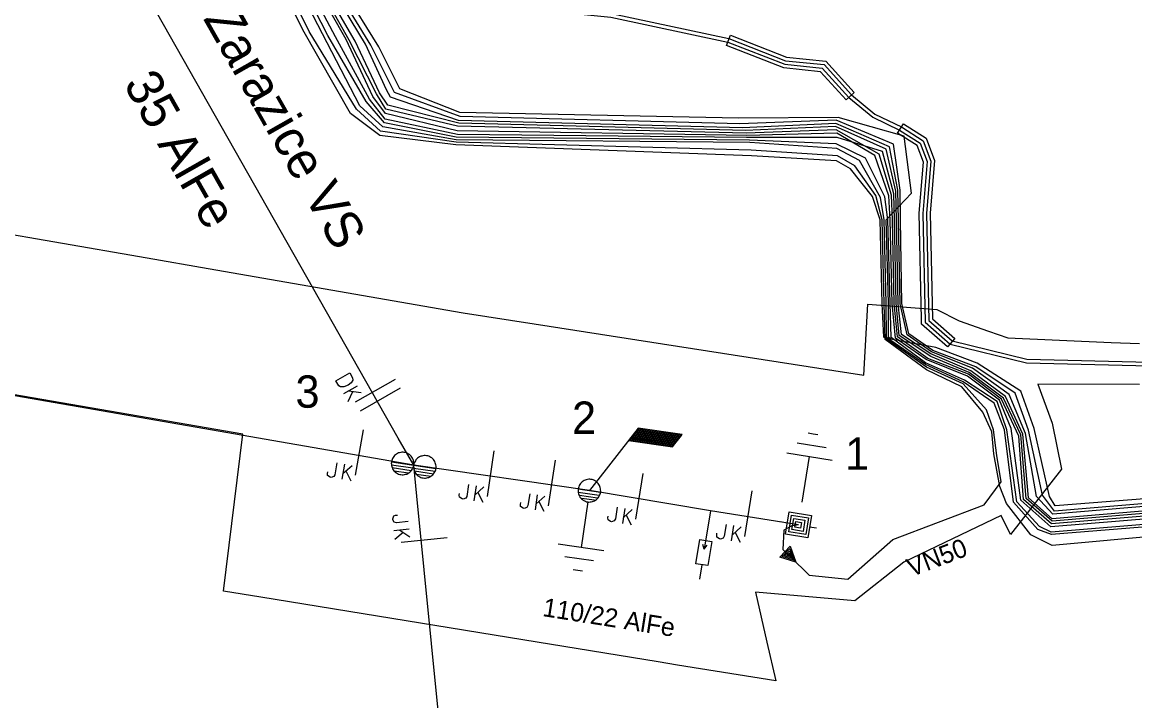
# Model space of a CAD drawing. Extents: x -545588 to -543214, y -1196037 to -1194452.
# Drawn here: x -545323 to -545262.7, y -1194915.7 to -1194878.9 of the extents above; entities that cross this region are included whole.
import ezdxf

# ---------------------------------------------------------------- set-up
doc = ezdxf.new("R2010")
doc.units = 0
for name, color, linetype in [('CIZÍ_NADZEM', 7, 'Continuous'), ('DOPLŇ_POPISY', 7, 'Continuous'), ('ELE_EON', 7, 'Continuous'), ('ELE_EON_POPIS', 7, 'Continuous'), ('Implicitní', 7, 'Continuous'), ('POL_ZNAČKA_PRACOVNÍ', 7, 'Continuous'), ('POL_ČÍSLO_PRACOVNÍ', 7, 'Continuous'), ('SDEL_EON_POPIS', 7, 'Continuous'), ('TECH_OCHR_PÁSMO_HRAN', 7, 'Continuous'), ('Vrstva 18', 7, 'Continuous'), ('Vrstva 19', 7, 'Continuous'), ('Vrstva 20', 7, 'Continuous'), ('Vrstva 35', 7, 'Continuous'), ('Vrstva 52', 7, 'Continuous'), ('Vrstva 53', 7, 'Continuous'), ('Vrstva 54', 7, 'Continuous'), ('ZP_EON', 7, 'Continuous')]:
    doc.layers.add(name, color=color, linetype=linetype)

# ---------------------------------------------------------------- blocks, each defined once
blk = doc.blocks.new('VN850')
at = {"layer": 'POL_ZNAČKA_PRACOVNÍ'}
for points in [[(-0.565, 1.426), (-0.565, -1.074)], [(-0.014, 1.426), (-0.014, -1.074)], [(-2.091, -0.542), (-1.776, -0.542)], [(-2.091, -1.409), (-2.091, -0.542)], [(-1.776, -0.542), (-1.657, -0.602)], [(-1.657, -0.602), (-1.588, -0.749)], [(-1.264, -0.542), (-1.264, -1.409)], [(-0.85, -0.542), (-1.264, -1.094)], [(-1.588, -1.202), (-1.667, -1.35)], [(-1.588, -0.749), (-1.549, -0.956)], [(-1.549, -0.956), (-1.588, -1.202)], [(-1.126, -0.917), (-0.772, -1.409)], [(-1.776, -1.409), (-2.091, -1.409)], [(-1.667, -1.35), (-1.776, -1.409)]]:
    blk.add_lwpolyline(points, dxfattribs=at)
blk = doc.blocks.new('VN840')
at = {"layer": 'POL_ZNAČKA_PRACOVNÍ'}
for points in [[(-0.009, 1.414), (-0.009, -1.086)], [(-1.092, -0.594), (-1.092, -1.243)], [(-0.678, -0.594), (-0.678, -1.421)], [(-0.678, -1.106), (-0.265, -0.594)], [(-1.505, -1.243), (-1.505, -1.145)], [(-0.541, -0.938), (-0.196, -1.421)], [(-1.476, -1.352), (-1.505, -1.243)], [(-1.328, -1.421), (-1.476, -1.352)], [(-1.269, -1.421), (-1.328, -1.421)], [(-1.131, -1.352), (-1.269, -1.421)], [(-1.092, -1.243), (-1.131, -1.352)]]:
    blk.add_lwpolyline(points, dxfattribs=at)
blk = doc.blocks.new('VN890')
at = {"layer": 'SDEL_EON_POPIS'}
for points in [[(-0.409, 0.411), (0.411, 0.001)], [(-0.409, -0.409), (-0.409, 0.411)], [(0.411, 0.001), (-0.409, -0.409)], [(-0.345, 0.31), (0.265, -0.003), (-0.345, -0.296), (-0.345, 0.31)], [(-0.264, 0.204), (0.104, 0.001), (-0.264, -0.183), (-0.264, 0.204)], [(-0.193, 0.094), (-0.045, 0.004), (-0.193, -0.08), (-0.193, 0.094)], [(-0.158, -0.009), (-0.158, 0.03), (-0.129, 0.007), (-0.158, -0.009)]]:
    blk.add_lwpolyline(points, dxfattribs=at)
blk = doc.blocks.new('VN820')
at = {"layer": 'DOPLŇ_POPISY'}
for points in [[(0.003, 0.002), (0.003, -2.105)], [(-0.322, -1.632), (0.338, -1.632)], [(-0.322, -2.951), (-0.322, -1.632)], [(0.338, -1.632), (0.338, -2.951)], [(0.003, -2.105), (-0.115, -1.859)], [(0.003, -2.105), (0.121, -1.859)], [(0.338, -2.951), (-0.322, -2.951)], [(0.003, -2.951), (0.003, -3.748)]]:
    blk.add_lwpolyline(points, dxfattribs=at)
blk = doc.blocks.new('VN810')
at = {"layer": 'POL_ZNAČKA_PRACOVNÍ'}
for points in [[(0.004, -1.247), (0.004, -3.747)], [(1.254, -3.747), (-1.246, -3.747)], [(0.772, -4.367), (-0.803, -4.367)], [(0.004, -4.997), (-0.252, -4.997)], [(0.27, -4.997), (0.004, -4.997)]]:
    blk.add_lwpolyline(points, dxfattribs=at)
blk = doc.blocks.new('VN450')
at = {"layer": 'ELE_EON_POPIS'}
for points in [[(0, 0), (-0.01, 0.13), (-0.03, 0.25), (-0.06, 0.38), (-0.11, 0.5), (-0.16, 0.61), (-0.23, 0.72), (-0.31, 0.82), (-0.4, 0.91), (-0.5, 0.99), (-0.61, 1.06), (-0.72, 1.11), (-0.84, 1.16), (-0.97, 1.19), (-1.09, 1.21), (-1.22, 1.22), (-1.35, 1.21), (-1.47, 1.19), (-1.59, 1.16), (-1.71, 1.11), (-1.83, 1.06), (-1.93, 0.99), (-2.03, 0.91), (-2.12, 0.82), (-2.2, 0.72), (-2.27, 0.61), (-2.33, 0.5), (-2.38, 0.38), (-2.41, 0.25), (-2.43, 0.13), (-2.44, 0), (-2.43, -0.13), (-2.41, -0.25), (-2.38, -0.38), (-2.33, -0.5), (-2.27, -0.61), (-2.2, -0.72), (-2.12, -0.82), (-2.03, -0.91), (-1.93, -0.99), (-1.83, -1.06), (-1.71, -1.11), (-1.59, -1.16), (-1.47, -1.19), (-1.35, -1.21), (-1.22, -1.22), (-1.09, -1.21), (-0.97, -1.19), (-0.84, -1.16), (-0.72, -1.11), (-0.61, -1.06), (-0.5, -0.99), (-0.4, -0.91), (-0.31, -0.82), (-0.23, -0.72), (-0.16, -0.61), (-0.11, -0.5), (-0.06, -0.38), (-0.03, -0.25), (-0.01, -0.13), (0, 0)], [(2.44, 0), (2.43, 0.13), (2.41, 0.25), (2.38, 0.38), (2.33, 0.5), (2.27, 0.61), (2.2, 0.72), (2.12, 0.82), (2.03, 0.91), (1.94, 0.99), (1.83, 1.06), (1.71, 1.11), (1.6, 1.16), (1.47, 1.19), (1.35, 1.21), (1.22, 1.22), (1.09, 1.21), (0.97, 1.19), (0.84, 1.16), (0.72, 1.11), (0.61, 1.06), (0.5, 0.99), (0.4, 0.91), (0.31, 0.82), (0.23, 0.72), (0.16, 0.61), (0.11, 0.5), (0.06, 0.38), (0.03, 0.25), (0.01, 0.13), (0, 0), (0.01, -0.13), (0.03, -0.25), (0.06, -0.38), (0.11, -0.5), (0.16, -0.61), (0.23, -0.72), (0.31, -0.82), (0.4, -0.91), (0.5, -0.99), (0.61, -1.06), (0.72, -1.11), (0.84, -1.16), (0.97, -1.19), (1.09, -1.21), (1.22, -1.22), (1.35, -1.21), (1.47, -1.19), (1.6, -1.16), (1.71, -1.11), (1.83, -1.06), (1.94, -0.99), (2.03, -0.91), (2.12, -0.82), (2.2, -0.72), (2.27, -0.61), (2.33, -0.5), (2.38, -0.38), (2.41, -0.25), (2.43, -0.13), (2.44, 0)], [(-2.44, 0), (2.44, 0)], [(-2.4, -0.31), (-0.04, -0.31)], [(-2.26, -0.61), (-0.17, -0.61)], [(-2.01, -0.92), (-0.42, -0.92)], [(0.04, -0.31), (2.4, -0.31)], [(0.17, -0.61), (2.27, -0.61)], [(0.42, -0.92), (2.02, -0.92)]]:
    blk.add_lwpolyline(points, dxfattribs=at)
blk = doc.blocks.new('VN001')
at = {"layer": 'Implicitní'}
for p, q in [((2.074, 3.631), (4.49, 3.631)), ((2.103, 3.681), (4.519, 3.681)), ((2.132, 3.731), (2.543, 3.731)), ((1.732, 3.031), (4.144, 3.031)), ((1.76, 3.081), (4.173, 3.081)), ((1.789, 3.131), (4.201, 3.131)), ((1.817, 3.181), (4.23, 3.181)), ((1.846, 3.231), (4.259, 3.231)), ((1.874, 3.281), (4.288, 3.281)), ((1.903, 3.331), (4.317, 3.331)), ((1.932, 3.381), (4.346, 3.381)), ((1.96, 3.431), (4.375, 3.431)), ((1.989, 3.481), (4.403, 3.481)), ((2.017, 3.531), (4.432, 3.531)), ((2.046, 3.581), (4.461, 3.581))]:
    blk.add_line(p, q, dxfattribs=at)
blk.add_lwpolyline([(2.132, 3.732), (0, 0)], dxfattribs=at)
blk.add_lwpolyline([(4.545, 3.727), (2.132, 3.732), (1.705, 2.984), (4.117, 2.985)], close=True, dxfattribs=at)
blk = doc.blocks.new('VN470')
at = {"layer": 'ELE_EON_POPIS'}
for points in [[(-1.23, 1.22), (1.23, 1.22)], [(-1.23, -1.23), (-1.23, 1.22)], [(0, 1.22), (0, 1.97)], [(1.23, 1.22), (1.23, -1.23)], [(-0.92, 0.9), (0.92, 0.9)], [(-0.92, -0.95), (-0.92, 0.9)], [(-0.61, 0.61), (0.61, 0.61)], [(-0.61, -0.62), (-0.61, 0.61)], [(-0.31, -0.27), (-0.31, 0.34)], [(-0.31, 0.34), (0.31, 0.34)], [(0.31, 0.34), (0.31, -0.27)], [(0.61, 0.61), (0.61, -0.62)], [(0.92, 0.9), (0.92, -0.95)], [(0.92, -0.95), (-0.92, -0.95)], [(0.61, -0.62), (-0.61, -0.62)], [(0.31, -0.27), (-0.31, -0.27)], [(1.23, -1.23), (-1.23, -1.23)], [(0, -1.23), (0, -1.98)]]:
    blk.add_lwpolyline(points, dxfattribs=at)
blk = doc.blocks.new('VN440')
at = {"layer": 'ELE_EON_POPIS'}
for points in [[(1.22, 0), (1.21, 0.13), (1.19, 0.25), (1.16, 0.38), (1.11, 0.5), (1.05, 0.61), (0.98, 0.72), (0.9, 0.82), (0.81, 0.91), (0.71, 0.99), (0.6, 1.06), (0.49, 1.12), (0.37, 1.16), (0.25, 1.2), (0.12, 1.22), (-0.01, 1.22), (-0.14, 1.22), (-0.26, 1.2), (-0.39, 1.16), (-0.51, 1.12), (-0.62, 1.06), (-0.73, 0.99), (-0.83, 0.91), (-0.92, 0.82), (-1, 0.72), (-1.07, 0.61), (-1.13, 0.5), (-1.18, 0.38), (-1.21, 0.25), (-1.23, 0.13), (-1.24, 0), (-1.23, -0.13), (-1.21, -0.26), (-1.18, -0.38), (-1.13, -0.5), (-1.07, -0.62), (-1, -0.73), (-0.92, -0.83), (-0.83, -0.92), (-0.73, -1), (-0.62, -1.07), (-0.51, -1.13), (-0.39, -1.17), (-0.26, -1.2), (-0.14, -1.23), (-0.01, -1.23), (0.12, -1.23), (0.25, -1.2), (0.37, -1.17), (0.49, -1.13), (0.6, -1.07), (0.71, -1), (0.81, -0.92), (0.9, -0.83), (0.98, -0.73), (1.05, -0.62), (1.11, -0.5), (1.16, -0.38), (1.19, -0.26), (1.21, -0.13), (1.22, 0)], [(-1.24, 0), (1.22, 0)], [(-1.18, -0.34), (1.1, -0.34)], [(-1.01, -0.63), (0.97, -0.63)], [(-0.74, -0.92), (0.68, -0.92)]]:
    blk.add_lwpolyline(points, dxfattribs=at)

msp = doc.modelspace()

# ---------------------------------------------------------------- linework, layer by layer
at = {"layer": 'ELE_EON'}
for points in [[(-545292.28, -1194904.3), (-545301.79, -1194902.92), (-545381.67, -1194889.04), (-545464.66, -1194874.97), (-545546.4, -1194860.3), (-545587.311, -1194845.749)], [(-545280.96, -1194906.15), (-545285.729, -1194905.392), (-545292.28, -1194904.3)]]:
    msp.add_lwpolyline(points, dxfattribs=at)
at = {"layer": 'Vrstva 20'}
for points in [[(-545284.859, -1194880.199), (-545284.641, -1194879.641), (-545281.609, -1194880.826), (-545279.475, -1194881.043), (-545277.938, -1194882.738), (-545278.382, -1194883.142), (-545279.765, -1194881.617), (-545281.751, -1194881.414)], [(-545273.703, -1194895.001), (-545272.493, -1194896.054), (-545272.887, -1194896.506), (-545274.297, -1194895.279), (-545274.302, -1194895.013), (-545274.42, -1194889.281), (-545274.194, -1194886.512), (-545274.526, -1194885.62), (-545275.589, -1194884.954), (-545275.271, -1194884.446), (-545274.034, -1194885.22), (-545273.586, -1194886.428), (-545273.821, -1194889.269)]]:
    msp.add_lwpolyline(points, close=True, dxfattribs=at)
at = {"layer": 'Vrstva 35'}
for points in [[(-545337.5, -1194888.01), (-545316.63, -1194891.63), (-545312.5, -1194892.35), (-545299.12, -1194894.67), (-545295.27, -1194895.27), (-545287.5, -1194896.47), (-545277.41, -1194898.04), (-545277.21, -1194894.2), (-545273.46, -1194894.5), (-545272.25, -1194895.11), (-545270.66, -1194895.66), (-545269.62, -1194896.02), (-545264.03, -1194896.28), (-545262.5, -1194896.33)], [(-545262.5, -1194898.55), (-545267.99, -1194898.54), (-545267.228, -1194900.65), (-545266.71, -1194903.14), (-545269.47, -1194906.68), (-545269.99, -1194905.64), (-545275.25, -1194908.18), (-545277.91, -1194910.26), (-545283.29, -1194909.8), (-545282.67, -1194912.5), (-545282.19, -1194914.6), (-545287.5, -1194913.74), (-545288.56, -1194913.56), (-545295.11, -1194912.5), (-545310.07, -1194910.07), (-545312.09, -1194909.74), (-545311.05, -1194901.24), (-545312.5, -1194900.99), (-545324.01, -1194899.01)]]:
    msp.add_lwpolyline(points, dxfattribs=at)
at = {"layer": 'Vrstva 52'}
msp.add_lwpolyline([(-545295.62, -1194964.78), (-545301.623, -1194904.598), (-545301.79, -1194902.92), (-545302.625, -1194901.45), (-545318.54, -1194873.42)], dxfattribs=at)
at = {"layer": 'ZP_EON'}
for points in [[(-545318.26, -1194854.24), (-545319.764, -1194855.371), (-545323.024, -1194860.428), (-545310.992, -1194874.793), (-545304.676, -1194875.756), (-545301.884, -1194877.567), (-545291.116, -1194878.669), (-545284.779, -1194880.016), (-545281.704, -1194881.218), (-545279.668, -1194881.426), (-545278.229, -1194883.012), (-545276.934, -1194884.085), (-545275.478, -1194884.788), (-545274.362, -1194885.487), (-545273.991, -1194886.484), (-545274.22, -1194889.287), (-545274.099, -1194895.186), (-545272.737, -1194896.371), (-545268.613, -1194897.38), (-545261.946, -1194897.55)], [(-545318.145, -1194854.404), (-545319.616, -1194855.509), (-545322.776, -1194860.412), (-545310.888, -1194874.607), (-545304.604, -1194875.564), (-545301.816, -1194877.373), (-545291.084, -1194878.471), (-545284.721, -1194879.824), (-545281.656, -1194881.022), (-545279.572, -1194881.234), (-545278.091, -1194882.868), (-545276.826, -1194883.915), (-545275.382, -1194884.612), (-545274.198, -1194885.353), (-545273.789, -1194886.456), (-545274.02, -1194889.293), (-545273.901, -1194895.094), (-545272.643, -1194896.189), (-545268.587, -1194897.18), (-545261.954, -1194897.35)], [(-545248.72, -1194905.18), (-545267.26, -1194906.67), (-545268, -1194906.41), (-545269.32, -1194904.93), (-545269.81, -1194901), (-545270.36, -1194899.57), (-545272.04, -1194898.4), (-545274.071, -1194897.475), (-545276.184, -1194896.005), (-545276.201, -1194894.148), (-545276.316, -1194889.638), (-545276.51, -1194888.43), (-545277.65, -1194886.42), (-545278.88, -1194885.77), (-545283.582, -1194885.46), (-545299.484, -1194885.308), (-545303.47, -1194884.61), (-545304.7, -1194883.47), (-545311.25, -1194870.82), (-545314.32, -1194865.11), (-545314.67, -1194864.22), (-545314.35, -1194862.78), (-545313.03, -1194861.76), (-545312.597, -1194861.441)], [(-545248.73, -1194904.4), (-545267.223, -1194905.96), (-545268.63, -1194904.731), (-545268.916, -1194901.286), (-545269.859, -1194899.284), (-545271.71, -1194897.9), (-545273.79, -1194897.04), (-545275.509, -1194895.899), (-545275.66, -1194894.15), (-545275.76, -1194889.647), (-545275.796, -1194888.232), (-545276.399, -1194885.93), (-545278.863, -1194885.175), (-545283.778, -1194885.175), (-545299.41, -1194885.02), (-545303.33, -1194884.18), (-545304.18, -1194883.1), (-545306.02, -1194879.74), (-545310.87, -1194870.61), (-545313.129, -1194866.04), (-545313.03, -1194865.13), (-545311.41, -1194864.14), (-545310.989, -1194863.845)], [(-545248.71, -1194904.72), (-545267.29, -1194906.26), (-545268.92, -1194904.81), (-545269.44, -1194900.94), (-545270.064, -1194899.408), (-545271.8, -1194898.11), (-545274.04, -1194897.2), (-545275.7, -1194896.04), (-545275.876, -1194894.165), (-545275.996, -1194889.643), (-545276.063, -1194888.347), (-545276.815, -1194886.164), (-545278.872, -1194884.953), (-545283.76, -1194885.07), (-545299.43, -1194884.82), (-545303.32, -1194883.88), (-545304.01, -1194882.97), (-545305.45, -1194879.87), (-545310.7, -1194870.63), (-545312.86, -1194865.98), (-545312.55, -1194865.37), (-545311.22, -1194864.41), (-545310.81, -1194864.123)], [(-545248.68, -1194904.56), (-545267.25, -1194906.09), (-545268.77, -1194904.77), (-545269.023, -1194901.357), (-545269.966, -1194899.355), (-545271.75, -1194898), (-545273.96, -1194897.15), (-545275.589, -1194895.975), (-545275.769, -1194894.17), (-545275.867, -1194889.647), (-545275.912, -1194888.298), (-545276.584, -1194886.092), (-545278.916, -1194884.757), (-545283.795, -1194884.953), (-545299.42, -1194884.56), (-545303.3, -1194883.65), (-545303.81, -1194882.81), (-545305.28, -1194879.91), (-545310.56, -1194870.54), (-545311.07, -1194868.58), (-545310.64, -1194867.91), (-545309.43, -1194867.05), (-545309.101, -1194866.84)], [(-545248.73, -1194904.26), (-545267.223, -1194905.818), (-545268.497, -1194904.695), (-545268.8, -1194901.233), (-545269.753, -1194899.204), (-545271.62, -1194897.81), (-545273.79, -1194896.9), (-545275.38, -1194895.84), (-545275.555, -1194894.192), (-545275.653, -1194889.647), (-545275.689, -1194888.08), (-545276.21, -1194885.807), (-545278.95, -1194884.58), (-545283.83, -1194884.81), (-545299.34, -1194884.41), (-545303.2, -1194883.43), (-545303.65, -1194882.76), (-545304.96, -1194879.97), (-545310.48, -1194870.49), (-545310.47, -1194869.52), (-545309.98, -1194868.83), (-545308.78, -1194868), (-545308.485, -1194867.803)], [(-545248.8, -1194904.02), (-545267.18, -1194905.57), (-545268.07, -1194904.61), (-545268.66, -1194901.21), (-545269.54, -1194899.09), (-545271.53, -1194897.66), (-545273.76, -1194896.79), (-545275.07, -1194895.87), (-545275.457, -1194894.179), (-545275.546, -1194889.656), (-545275.582, -1194888.027), (-545276.031, -1194885.692), (-545278.94, -1194884.43), (-545283.99, -1194884.66), (-545299.36, -1194884.26), (-545303.04, -1194882.99), (-545303.27, -1194882.6), (-545304.4, -1194880.12), (-545310.24, -1194870.45), (-545310.23, -1194869.82), (-545309.76, -1194869.17), (-545308.57, -1194868.32), (-545308.257, -1194868.111)], [(-545248.86, -1194903.88), (-545267.1, -1194905.41), (-545267.75, -1194904.54), (-545268.5, -1194901.02), (-545269.22, -1194899.03), (-545271.359, -1194897.6), (-545273.69, -1194896.71), (-545274.99, -1194895.81), (-545275.36, -1194894.17), (-545275.44, -1194889.63), (-545275.449, -1194888.027), (-545275.82, -1194885.54), (-545278.92, -1194884.25), (-545284.13, -1194884.44), (-545299.28, -1194884.04), (-545302.83, -1194882.74), (-545304.12, -1194880.18), (-545309.29, -1194871.74), (-545309.64, -1194870.67), (-545309.23, -1194869.91), (-545308.02, -1194869.17), (-545307.661, -1194868.936)], [(-545248.84, -1194903.69), (-545267.05, -1194905.12), (-545267.37, -1194904.62), (-545268.19, -1194900.93), (-545268.92, -1194898.92), (-545271.28, -1194897.4), (-545273.52, -1194896.55), (-545275.957, -1194896.094), (-545276.077, -1194895.999), (-545276.085, -1194894.152), (-545276.214, -1194889.643), (-545274.84, -1194888.2), (-545275.24, -1194885.1), (-545278.81, -1194884.1), (-545284.21, -1194884.13), (-545299.29, -1194883.82), (-545302.55, -1194882.54), (-545303.68, -1194880.28), (-545309.26, -1194871.27), (-545309.01, -1194870.25), (-545307.81, -1194869.43), (-545307.472, -1194869.214)], [(-545248.71, -1194905.01), (-545267.267, -1194906.539), (-545267.9, -1194906.24), (-545269.129, -1194904.91), (-545269.67, -1194901.01), (-545270.198, -1194899.48), (-545271.97, -1194898.314), (-545274.08, -1194897.377), (-545275.94, -1194896.01), (-545275.983, -1194894.152), (-545276.116, -1194889.638), (-545276.28, -1194888.4), (-545277.33, -1194886.3), (-545278.91, -1194885.52), (-545283.6, -1194885.327), (-545299.49, -1194885.17), (-545303.37, -1194884.38), (-545304.36, -1194883.24), (-545306.44, -1194879.65), (-545311.05, -1194870.68)], [(-545280.96, -1194906.15), (-545281.35, -1194906.22), (-545281.75, -1194906.44), (-545281.81, -1194907.48), (-545281.387, -1194907.886), (-545280.37, -1194908.87), (-545278.28, -1194909.1), (-545275.84, -1194906.95), (-545270.91, -1194905.07), (-545269.976, -1194903.823), (-545270.22, -1194902.39), (-545270.39, -1194901.01), (-545270.78, -1194899.92), (-545272.04, -1194898.52), (-545274.027, -1194897.61), (-545276.335, -1194895.985), (-545276.42, -1194894.18), (-545276.54, -1194889.64), (-545276.94, -1194888.38), (-545278.14, -1194886.88), (-545278.89, -1194886.45), (-545283.5, -1194886.17), (-545299.51, -1194885.57), (-545303.63, -1194885.07), (-545305.21, -1194883.88), (-545307.79, -1194879.36), (-545311.89, -1194871)], [(-545248.61, -1194905.57), (-545267.22, -1194907.27), (-545268.37, -1194906.69), (-545269.69, -1194905), (-545270.056, -1194904.082), (-545270.38, -1194902.31), (-545270.48, -1194901.12), (-545270.97, -1194900.05), (-545272.12, -1194898.68), (-545274.02, -1194897.75), (-545276.27, -1194896.11), (-545276.316, -1194894.192), (-545276.428, -1194889.638), (-545276.771, -1194888.321), (-545277.91, -1194886.71), (-545278.84, -1194886.18), (-545283.52, -1194885.86), (-545299.484, -1194885.433), (-545303.58, -1194884.84), (-545304.89, -1194883.64), (-545307.45, -1194879.44), (-545311.66, -1194870.97)]]:
    msp.add_lwpolyline(points, dxfattribs=at)

# ---------------------------------------------------------------- block references
at = {"layer": 'DOPLŇ_POPISY'}
for name, p, xscale, yscale, rotation in [('VN450', (-545301.791, -1194902.92), 0.49999999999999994, 0.49999999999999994, -8.512510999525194), ('VN440', (-545292.274, -1194904.299), 0.5, 0.4999999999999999, -8.256972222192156), ('VN470', (-545280.96, -1194906.151), 0.5, 0.5000000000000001, 80.65912772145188)]:
    msp.add_blockref(name, p, dxfattribs=dict(at, xscale=xscale, yscale=yscale, rotation=rotation))
at = {"layer": 'POL_ZNAČKA_PRACOVNÍ'}
for p, rotation in [((-545280.96, -1194906.15), 170.7505444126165), ((-545292.191, -1194903.673), -8.264269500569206)]:
    msp.add_blockref('VN810', p, dxfattribs=dict(at, rotation=rotation))
at = {"layer": 'POL_ČÍSLO_PRACOVNÍ', "rotation": -9.029133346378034}
msp.add_blockref('VN820', (-545285.729, -1194905.392), dxfattribs=at)
at = {"layer": 'TECH_OCHR_PÁSMO_HRAN', "rotation": -8.254969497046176}
msp.add_blockref('VN001', (-545292.28, -1194904.296), dxfattribs=at)
at = {"layer": 'Vrstva 18'}
for name, p, rotation in [('VN850', (-545303.749, -1194899.47), -60.412235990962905), ('VN840', (-545304.766, -1194902.402), -9.857330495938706), ('VN840', (-545297.647, -1194903.544), -8.565930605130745), ('VN840', (-545294.339, -1194904.042), -8.56593047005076), ('VN840', (-545289.599, -1194904.778), -9.024833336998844), ('VN840', (-545283.703, -1194905.715), -9.02483334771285), ('VN840', (-545301.382, -1194907.004), -84.3081111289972)]:
    msp.add_blockref(name, p, dxfattribs=dict(at, rotation=rotation))
at = {"layer": 'Vrstva 19', "rotation": -43.88652780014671}
msp.add_blockref('VN890', (-545281.388, -1194907.886), dxfattribs=at)

# ---------------------------------------------------------------- texts
at = {"layer": 'CIZÍ_NADZEM'}
msp.add_text('VN50', height=1, rotation=20.874, dxfattribs=at).set_placement((-545274.846, -1194908.982))
at = {"layer": 'ELE_EON_POPIS'}
msp.add_text('110/22 AlFe', height=1, rotation=350.98, dxfattribs=at).set_placement((-545294.852, -1194911.085))
at = {"layer": 'POL_ZNAČKA_PRACOVNÍ'}
for s, p in [('3', (-545308.19, -1194899.81)), ('2', (-545293.217, -1194901.225)), ('1', (-545278.43, -1194903.167))]:
    msp.add_text(s, height=1.75, dxfattribs=at).set_placement(p)
at = {"layer": 'Vrstva 53'}
msp.add_text('35 AlFe', height=2, rotation=299.588, dxfattribs=at).set_placement((-545317.535, -1194882.287))
at = {"layer": 'Vrstva 54'}
msp.add_text('o.Zarazice VS', height=2, rotation=299.588, dxfattribs=at).set_placement((-545314.315, -1194876.802))

doc.saveas('drawing.dxf')
